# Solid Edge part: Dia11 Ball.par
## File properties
Title: Dia10,3 Ball
Author: Dan
Template: Normal.par
Last saved by: Dan
Revision: 8
Application: Solid Edge
Density: 0 kg/mm^3
Accuracy: 0.99
Document Number: P52-013
Project Name: Piston Pump P52
Material: steel
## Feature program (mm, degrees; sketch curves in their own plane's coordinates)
sketch for "unnamed RevolvedProtrusion 1" plane through (0, 0, 0) normal (0, -1, 0) x-axis (1, 0, 0)
  arc centre (0, 0) radius 5.5 from (-5.5, 0) to (5.5, 0) cw
revolve "unnamed RevolvedProtrusion 1" add full turn 360 deg about sketch line (-5.5, 0) -> (5.5, 0)
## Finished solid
Body 1: solid body, 1 face, 0 edges, 0 vertices.
  Faces by surface: sphere 1
Spherical faces by radius (mm): R5.5 x1
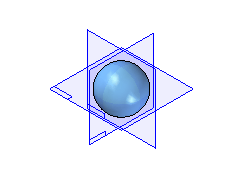
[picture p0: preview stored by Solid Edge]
